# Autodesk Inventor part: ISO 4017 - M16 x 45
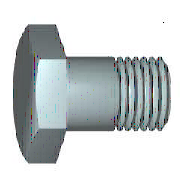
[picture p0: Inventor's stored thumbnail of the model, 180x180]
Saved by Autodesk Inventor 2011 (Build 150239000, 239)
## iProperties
IsCustomPart: 0
Created: 2009-02
Part Number: ISO 4017 - M16 x 45
Material: Stainless Steel, 440C
Description: Hexagon head screws
Document SubType Name: Modeling
Standard: ISO 4017
Designer: V.de Jong
Standard Revision: Third edition 1999-08-15
Standards Organization: ISO
Language: en-US
Size Designation: M16 x 45
Categories: <MemberInstance><Categories><Category DisplayName="Fasteners" InternalName="e4da775c-781d-43d5-af7c-5136215cf5a6" Mnemonic="FSTN"><Category DisplayName="Bolts"
Density: 7.75 g/cm^3
Mass: 107.756 g
Surface Area: 40.1955 cm^2
Volume: 13.904 cm^3
Author: V.de Jong
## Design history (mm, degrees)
body "Solid1"
workplane "Work Plane1"
revolve "Body" stored, may be unused: angle "d12" = 90 deg
sketch "Sketch2"
  geometry: L1 (0, 13.856)-(12, 6.928); L2 (12, 6.928)-(12, -6.928); L3 (12, -6.928)-(0, -13.856); L4 (0, -13.856)-(-12, -6.928); L5 (-12, -6.928)-(-12, 6.928); L6 (-12, 6.928)-(0, 13.856); 2 further points
  constraints: 12 end point, 1 coincident, 1 vertical, 11 other
  dimensions: "d11" = 24 distance between parallel lines of L5 L2 (= SW)
extrude "Head" join sketch "Sketch2" distance "d3" = 9.2 (= KOH - SD); taper "d4" = 0 deg
revolve "Chamfer1" stored, may be unused: angle "d21" = 90 deg
feature "Thread" dims "d15" = 39 (= GEL), "d16" = 0
chamfer "Chamfer2" distance "d6" = 1.2269 (= -0.5 x SPD + 0.5 x GD); stored, may be unused: second distance "d7" = 1.227 (computed from GUL), angle "d55" = 45 deg
sketch "Sketch1"
  geometry: L1 (0, 11.245)-(0, 8); L2 (6, 8)-(45, 8); L3 (45, 8)-(45, 0); L4 (45, 0)-(-0.8, 0); L5 (-9.96, 0)-(54.16, 0) reference; L6 (-0.8, 0)-(-0.8, 11.245); L7 (-0.8, 11.245)-(0, 11.245); L8 (6, 8)-(4.773, 8); L9 (4.773, 8)-(0, 8); L10 (0, -2.249)-(0, 13.494) reference
  constraints: 16 end point, 2 collinear, 2 perpendicular, 1 parallel
  dimensions: "d0" = 45 distance between parallel lines of L3 L1 (= NLG); "d1" = 39 distance from line of L2.start L3 (= GEL); "d2" = 16 diameter of L2 L4 (= GD); "d9" = 0.8001 distance between parallel lines of L6 L1 (computed from SD); "d10" = 22.49 diameter of L7 L4 (= SD2); "d13" = 1.227 distance of L2.start L8.end (computed from GAL); "d14" = 16 diameter of L9 L4 (= BDM)
sketch "Sketch4"
  geometry: L1 (-10, 12)-(-10, 13.856); L2 (-10, 13.856)-(-8.928, 13.856); L3 (-8.928, 13.856)-(-10, 12); L4 (-11.84, 0)-(1.04, 0) reference; L5 (-0.8, 13.856)-(-10, 13.856) reference; L6 (-10, 6.928)-(-10, 13.856) reference
  constraints: 6 end point, 2 collinear, 1 perpendicular, 1 vertical
  dimensions: "d5" = 30 deg angle of L3 L1 (= ANG1); "d19" = 24 diameter of L1.start L4 (= SW0)
other parameters: "NLG" = 45 [user parameter; used in 1 equation term], "GD" = 16 (= NND) [user parameter; used in 2 equation terms], "BDM" = 16 (= NND) [user parameter; used in 1 equation term], "KOH" = 10 [user parameter; used in 1 equation term], "GEL" = 39 [user parameter; used in 2 equation terms], "SW" = 24 [user parameter; used in 2 equation terms], "SW0" = 24 (= SW) [user parameter; used in 1 equation term], "SPD" = 13.5462 (= NND - 1.2269 x PTC) [user parameter; used in 1 equation term], "SD2" = 22.49 [user parameter; used in 2 equation terms], "SD" = 0.8 [user parameter; used in 2 equation terms], "ANG1" = 30 deg [user parameter; used in 1 equation term], "GAL" = 1.2269 (= 0.61345 x PTC) [user parameter; used in 1 equation term], "GUL" = 1.2269 (= 0.61345 x PTC) [user parameter; used in 1 equation term], "d8" = 0, "RR" = 0.6 [user parameter], "d57" = 0, "d58" = 0, "TPU" = 5 (computed from PTC) [user parameter], "GD1" = 13.5462 (= THREADDIA - 1.2269 x PTC) [user parameter], "THREADDIA" = 16 [user parameter; used in 1 equation term], "SDH" = 22.49 (= SD2) [user parameter], "SDHG" = 6 [user parameter], "TOA" = 30 deg [user parameter], "PTC" = 2 [user parameter; used in 5 equation terms], "NND" = 16 [user parameter; used in 3 equation terms], "E0" = 27.72 [user parameter]
